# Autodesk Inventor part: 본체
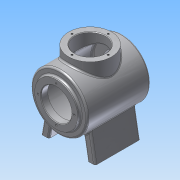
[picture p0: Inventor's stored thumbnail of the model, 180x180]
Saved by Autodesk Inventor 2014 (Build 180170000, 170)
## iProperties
Created: 2015-01
Part Number: 본체
Material: 알루미늄 6061
Document SubType Name: Modeling
Designer: user
Density: 2.71 g/cm^3
Appearance: 알루미늄 - 평지
Mass: 1007 g
Surface Area: 1053.24 cm^2
Volume: 371.588 cm^3
Author: user
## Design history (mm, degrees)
sketch "스케치1"
  geometry: C1 r 50 at (0, 0); C2 r 38 at (0, 0); 1 further point
  constraints: 2 centre point, 1 coincident, 1 concentric
  dimensions: "d0" = 76 diameter of C2; "d1" = 100 diameter of C1
extrude "돌출1" new body sketch "스케치1" stored distance "d2" = 112; taper "d3" = 0 deg
extrude "돌출2" join sketch "스케치1" stored distance "d4" = 122; taper "d5" = 0 deg
sketch "스케치2" dims "d6" = 64
  geometry: 3 further points
  constraints: 2 vertical alignment, 1 coincident, 2 other
hole "구멍1" sketch "스케치2" at (0, 32) diameter "d7" = 3.242; stored, may be unused: countersink angle "d11" = 90 deg, drill point angle "d13" = 118 deg; dims "d8" = 8, "d9" = 4, "d10" = 2, "d12" = 10
hole "구멍2" diameter "d19" = 54; stored, may be unused: countersink angle "d23" = 90 deg, drill point angle "d25" = 0 deg; dims "d17" = 10, "d18" = 10, "d20" = 8, "d21" = 4, "d22" = 2, "d24" = 12
hole "구멍3" diameter "d28" = 90; stored, may be unused: countersink angle "d32" = 90 deg, drill point angle "d34" = 0 deg; dims "d26" = 10, "d27" = 10, "d29" = 8, "d30" = 4, "d31" = 2, "d33" = 97
hole "구멍4" diameter "d37" = 54; stored, may be unused: countersink angle "d41" = 90 deg, drill point angle "d43" = 0 deg; dims "d35" = 10, "d36" = 10, "d38" = 8, "d39" = 4, "d40" = 2, "d42" = 13
sketch "스케치3"
  geometry: L1 (34, -80)-(48, -80); L2 (48, -80)-(39.336, -30.865); L3 (34, -80)-(27.282, -41.901); L4 (-39.336, -30.865)-(-48, -80); L5 (-48, -80)-(-34, -80); L6 (-34, -80)-(-27.282, -41.901); A1 r 50 centre (0, 0) between (39.336, -30.865) and (27.282, -41.901) reference; 1 further point
  constraints: 12 end point, 4 point on circle, 3 equal length, 2 collinear, 1 horizontal, 1 horizontal alignment
  dimensions: "d44" = 80 distance from line of point (0, 0) L1; "d45" = 14 distance of L1.start L1.end; "d46" = 100 deg angle of L1 L2; "d87" = 80 deg angle of L1 L3; "d88" = 96 distance of L1.end L4.end
extrude "돌출3" join sketch "스케치3" stored distance "d47" = 80; taper "d48" = 0 deg
node "작업 평면1"
sketch "스케치4"
  geometry: L1 (-86, -101)-(-10, -101) reference; C1 r 38 at (-48, -39); 2 further points
  constraints: 1 centre point, 1 midpoint, 1 vertical alignment
  dimensions: "d50" = 76 diameter of C1; "d51" = 62 distance from line of C1.centre L1
extrude "돌출4" join sketch "스케치4" stored distance "d52" = 80; taper "d53" = 0 deg
sketch "스케치5" dims "d54" = 64
  geometry: C1 r 38 at (0, 0) reference; 3 further points
  constraints: 2 vertical alignment, 3 other
hole "구멍5" sketch "스케치5" at (0, 32) diameter "d55" = 3.242; stored, may be unused: countersink angle "d59" = 90 deg, drill point angle "d61" = 118 deg; dims "d56" = 8, "d57" = 4, "d58" = 2, "d60" = 10
node "작업축1"
node "작업 평면3"
  node "작업 평면2"
sketch "스케치6"
  geometry: L1 (-6, 28)-(6, 28); L2 (6, 28)-(6, -26); L3 (6, -26)-(-6, -26); L4 (-6, -26)-(-6, 28); L5 (-62, -37)-(-62, 39) reference; L6 (-38, -61)-(38, -61) reference; 5 further points
  constraints: 8 end point, 4 midpoint, 2 parallel, 1 horizontal, 1 horizontal alignment, 1 perpendicular, 1 vertical alignment
  dimensions: "d66" = 54 distance of L1.end L2.end; "d67" = 12 distance of L2.end L3.end
extrude "돌출5" join sketch "스케치6" stored distance "d68" = 80; taper "d69" = 0 deg
sketch "스케치7"
  geometry: L1 (-26, 6)-(28, 6) reference; L2 (28, 6)-(28, -6) reference; 4 further points
  constraints: 2 midpoint, 1 horizontal alignment, 1 vertical alignment, 1 other
feature "엠보싱1" sketch "스케치7" dims "d24" = 12, "d70" = 0.5, "d71" = 0
hole "구멍6" diameter "d74" = 54; stored, may be unused: countersink angle "d78" = 90 deg, drill point angle "d80" = 0 deg; dims "d72" = 10, "d73" = 10, "d75" = 8, "d76" = 4, "d77" = 2, "d79" = 10
chamfer "모따기1" distance "d81" = 1; stored, may be unused: second distance "d82" = 2, angle "d83" = 45 deg
fillet "모깎기1" dims "d84" = 3
fillet "모깎기2" dims "d85" = 3
fillet "모깎기3" dims "d86" = 3
node "솔리드1"
pattern_circular "원형 패턴1" dims angle "d15" = 360 deg
mirror "대칭1"
pattern_circular "원형 패턴2" dims angle "d63" = 360 deg
other parameters: "d49" = -142, "d65" = -2
